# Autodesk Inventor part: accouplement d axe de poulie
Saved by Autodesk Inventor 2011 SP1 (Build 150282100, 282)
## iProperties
Created: 2010-12
Part Number: accouplement d axe de poulie
Document SubType Name: Modeling
Designer: eric
Density: 1 g/cm^3
Mass: 1.95689 g
Surface Area: 29.7358 cm^2
Volume: 1.95689 cm^3
Author: eric
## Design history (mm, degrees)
feature "Base1"
node "Solide1"
node "Corps solides"
node "Corps surfaciques"
